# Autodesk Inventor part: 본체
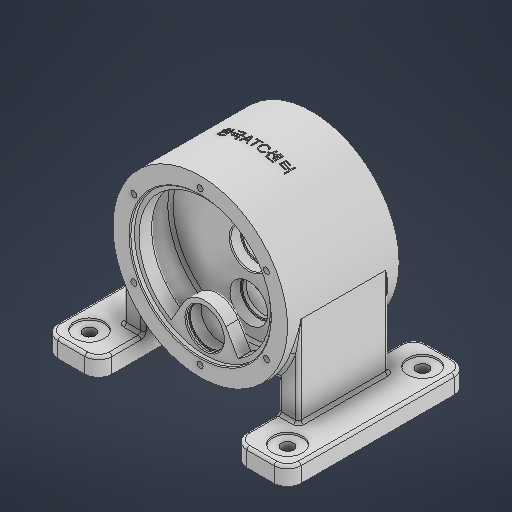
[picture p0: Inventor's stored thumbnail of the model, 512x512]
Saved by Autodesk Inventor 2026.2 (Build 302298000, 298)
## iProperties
Created: 2025-12
Part Number: 본체
Material: 일반
Document SubType Name: Modeling
Designer: PC2-07
Density: 1 g/cm^3
Appearance: 기본값
Author: PC2-07
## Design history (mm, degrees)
sketch "스케치1"
  geometry: C1 r 97 at (0, 0); 1 further point
  constraints: 1 centre point, 1 coincident
  dimensions: "d0" = 194 diameter of C1
extrude "돌출1" new body sketch "스케치1" stored distance "d1" = 124; taper "d2" = 0 deg
sketch "스케치2"
  geometry: L1 (97, -62)-(-97, -62) reference; L2 (-97, -62)-(-97, 62) reference; L3 (-97, 62)-(97, 62) reference; L4 (97, 62)-(97, -62) reference; L5 (0, 62)-(0, -62); L6 (78, 62)-(78, 57); L7 (78, 57)-(73, 57); L8 (73, 57)-(73, 43); L9 (76, 40)-(84, 40); L10 (87, 37)-(87, 11); L11 (84, 8)-(22, 8); L12 (21, 7)-(21, -3.4); L13 (20.4, -4)-(19, -4); L14 (19, -4)-(19, -8); L15 (19, -8)-(84, -8); L16 (87, -11)-(87, -37); L17 (84, -40)-(76, -40); L18 (73, -43)-(73, -57); L19 (73, -57)-(78, -57); L20 (78, -57)-(78, -62); L21 (22, 8)-(21, 7); A1 r 0.6 centre (20.4, -3.4) between (20.4, -4) and (21, -3.4); A2 r 3 centre (84, 37) between (87, 37) and (84, 40); A3 r 3 centre (84, 11) between (84, 8) and (87, 11); A4 r 3 centre (84, -11) between (87, -11) and (84, -8); A5 r 3 centre (84, -37) between (84, -40) and (87, -37); A6 r 3 centre (76, -43) between (76, -40) and (73, -43); A7 r 3 centre (76, 43) between (73, 43) and (76, 40); 6 further points
  constraints: 34 end point, 14 point on circle, 14 point on line, 14 tangent, 10 perpendicular, 7 centre point, 3 equal radius, 3 vertical, 2 midpoint, 1 horizontal
  dimensions: "d3" = 156 diameter of L6 L5; "d4" = 146 diameter of L8 L5; "d5" = 174 diameter of L10 L5; "d6" = 42 diameter of L12 L5; "d7" = 38 diameter of L14 L5; "d8" = 146 diameter of L18 L5; "d9" = 156 diameter of L20 L5; "d10" = 5 distance of L6.start L6.end; "d11" = 22 distance between parallel lines of L3 L9; "d12" = 32 distance of point (87, 40) point (87, 8); "d13" = 32 distance of point (87, -8) point (87, -40); "d14" = 5 distance of L19.end L20.end; "d16" = 22 distance between parallel lines of L1 L17; "d17" = 66 distance between parallel lines of L3 L13; "d18" = 0.6 radius of A1; "d19" = 3 radius of A2; "d20" = 3 radius of A6 (derived); "d21" = 3 radius of A7 (derived); "d22" = 1 distance of L11.end point (21, 8); "d23" = 1 distance of L12.start point (21, 8) (= d22)
revolve "회전1" sketch "스케치2" stored, may be unused: angle "d24" = 90 deg
sketch "스케치4"
  geometry: L1 (78, -62)-(78, -57) reference; L2 (78, -57)-(73, -57) reference; L3 (73, -57)-(73, -43) reference; L4 (76, -40)-(84, -40) reference; L5 (87, -37)-(87, -11) reference; L6 (84, -8)-(19, -8) reference; L7 (19, -8)-(19, -4) reference; L8 (19, -4)-(20.4, -4) reference; L9 (21, -3.4)-(21, 7) reference; L10 (21, 7)-(22, 8) reference; L11 (22, 8)-(84, 8) reference; L12 (87, 11)-(87, 37) reference; L13 (84, 40)-(76, 40) reference; L14 (73, 43)-(73, 57) reference; L15 (73, 57)-(78, 57) reference; L16 (78, 57)-(78, 62) reference; L17 (78, 62)-(97, 62) reference; L18 (97, 62)-(97, -62) reference; L19 (97, -62)-(78, -62) reference; L20 (-78, -57)-(-78, -62) reference; L21 (-78, -62)-(-97, -62) reference; L22 (-97, -62)-(-97, 62) reference; L23 (-97, 62)-(-78, 62) reference; L24 (-78, 62)-(-78, 57) reference; L25 (-78, 57)-(-73, 57) reference; L26 (-76, 40)-(-84, 40) reference; L27 (-87, 37)-(-87, 11) reference; L28 (-84, 8)-(-22, 8) reference; L29 (-22, 8)-(-21, 7) reference; L30 (-21, 7)-(-21, -3.4) reference; L31 (-20.4, -4)-(-19, -4) reference; L32 (-19, -4)-(-19, -8) reference; L33 (-19, -8)-(-84, -8) reference; L34 (-87, -11)-(-87, -37) reference; L35 (-84, -40)-(-76, -40) reference; L36 (-73, -43)-(-73, -57) reference; L37 (-73, -57)-(-78, -57) reference; L38 (0, 0)-(-52.5, 0); L39 (-52.5, 0)-(-52.5, 62); L40 (-52.5, 0)-(-52.5, -62); L41 (78, -62)-(-78, -62) reference; L42 (-31.5, 57)-(-31.5, 53.95); L43 (-31.5, 53.95)-(-30.25, 53.95); L44 (-30.25, 53.95)-(-30.25, 52); L45 (-30.25, 52)-(-31.5, 52); L46 (-31.5, 52)-(-31.5, 40); L47 (-73, 57)-(-73, 43) reference; A1 r 3 centre (76, -43) between (76, -40) and (73, -43) reference; A2 r 3 centre (84, -37) between (84, -40) and (87, -37) reference; A3 r 3 centre (84, -11) between (87, -11) and (84, -8) reference; A4 r 0.6 centre (20.4, -3.4) between (20.4, -4) and (21, -3.4) reference; A5 r 3 centre (84, 11) between (84, 8) and (87, 11) reference; A6 r 3 centre (84, 37) between (87, 37) and (84, 40) reference; A7 r 3 centre (76, 43) between (73, 43) and (76, 40) reference; A8 r 3 centre (-76, 43) between (-76, 40) and (-73, 43) reference; A9 r 3 centre (-84, 37) between (-84, 40) and (-87, 37) reference; A10 r 3 centre (-84, 11) between (-87, 11) and (-84, 8) reference; A11 r 0.6 centre (-20.4, -3.4) between (-21, -3.4) and (-20.4, -4) reference; A12 r 3 centre (-84, -11) between (-84, -8) and (-87, -11) reference; A13 r 3 centre (-84, -37) between (-87, -37) and (-84, -40) reference; A14 r 3 centre (-76, -43) between (-73, -43) and (-76, -40) reference
  constraints: 16 end point, 3 vertical, 2 horizontal, 2 perpendicular, 2 point on line
  dimensions: "d32" = 52.5 distance of L38.start L38.end; "d33" = 44.5 diameter of L44 L39; "d34" = 1.95 distance of L43.end L44.end; "d35" = 12 distance of L45.end L46.end; "d36" = 42 diameter of L46 L39; "d37" = 42 diameter of L42 L39
  node "절단 모서리 투영2"
node "작업 평면2"
sketch "스케치5"
  geometry: L1 (0, 0)-(0, -52.5); L2 (-23.383, -39)-(-49.148, -83.627); L3 (0, -52.5)-(0, -97); L4 (23.383, -39)-(49.148, -83.627); C1 r 84 at (0, 0) reference; C2 r 76 at (0, 0) reference; A1 r 27 centre (0, -52.5) between (23.383, -39) and (-23.383, -39); A2 r 97 centre (0, 0) between (-49.148, -83.627) and (0, -97) reference; 2 further points
  constraints: 8 end point, 4 point on circle, 2 symmetric about line, 2 vertical, 1 centre point, 1 coincident, 1 tangent
  dimensions: "d41" = 52.5 distance of L1.start L1.end; "d42" = 54 diameter of A1; "d43" = 30 deg angle of L2 L3
extrude "돌출3" join sketch "스케치5" distance "d44" = 17; taper "d45" = 0 deg
sketch "스케치6"
  geometry: L1 (0, 0)-(-52.5, 0); L2 (-52.5, 0)-(-52.5, 62); L3 (-78, 62)-(78, 62) reference; L4 (78, -62)-(78, -57) reference; L5 (78, -57)-(73, -57) reference; L6 (73, -57)-(73, -43) reference; L7 (76, -40)-(84, -40) reference; L8 (87, -37)-(87, -11) reference; L9 (84, -8)-(19, -8) reference; L10 (19, -8)-(19, -4) reference; L11 (19, -4)-(20.4, -4) reference; L12 (21, -3.4)-(21, 7) reference; L13 (21, 7)-(22, 8) reference; L14 (22, 8)-(84, 8) reference; L15 (87, 11)-(87, 37) reference; L16 (84, 40)-(76, 40) reference; L17 (73, 43)-(73, 57) reference; L18 (73, 57)-(78, 57) reference; L19 (78, 57)-(78, 62) reference; L20 (78, 62)-(97, 62) reference; L21 (97, 62)-(97, -62) reference; L22 (97, -62)-(78, -62) reference; L23 (-78, -57)-(-78, -62) reference; L24 (-78, -62)-(-97, -62) reference; L25 (-97, -62)-(-97, 62) reference; L26 (-97, 62)-(-78, 62) reference; L27 (-78, 62)-(-78, 57) reference; L28 (-78, 57)-(-25.5, 57) reference; L29 (-25.5, 57)-(-25.5, 40) reference; L30 (-25.5, 40)-(-84, 40) reference; L31 (-87, 37)-(-87, 11) reference; L32 (-84, 8)-(-22, 8) reference; L33 (-22, 8)-(-21, 7) reference; L34 (-21, 7)-(-21, -3.4) reference; L35 (-20.4, -4)-(-19, -4) reference; L36 (-19, -4)-(-19, -8) reference; L37 (-19, -8)-(-84, -8) reference; L38 (-87, -11)-(-87, -37) reference; L39 (-84, -40)-(-76, -40) reference; L40 (-73, -43)-(-73, -57) reference; L41 (-73, -57)-(-78, -57) reference; L42 (-31.5, 57)-(-31.5, 53.95); L43 (-31.5, 53.95)-(-30.25, 53.95); L44 (-30.25, 53.95)-(-30.25, 52); L45 (-30.25, 52)-(-31.5, 52); L46 (-31.5, 52)-(-31.5, 40); A1 r 3 centre (76, -43) between (76, -40) and (73, -43) reference; A2 r 3 centre (84, -37) between (84, -40) and (87, -37) reference; A3 r 3 centre (84, -11) between (87, -11) and (84, -8) reference; A4 r 0.6 centre (20.4, -3.4) between (20.4, -4) and (21, -3.4) reference; A5 r 3 centre (84, 11) between (84, 8) and (87, 11) reference; A6 r 3 centre (84, 37) between (87, 37) and (84, 40) reference; A7 r 3 centre (76, 43) between (73, 43) and (76, 40) reference; A8 r 3 centre (-84, 37) between (-84, 40) and (-87, 37) reference; A9 r 3 centre (-84, 11) between (-87, 11) and (-84, 8) reference; A10 r 0.6 centre (-20.4, -3.4) between (-21, -3.4) and (-20.4, -4) reference; A11 r 3 centre (-84, -11) between (-84, -8) and (-87, -11) reference; A12 r 3 centre (-84, -37) between (-87, -37) and (-84, -40) reference; A13 r 3 centre (-76, -43) between (-73, -43) and (-76, -40) reference; 2 further points
  constraints: 14 end point, 4 perpendicular, 3 point on line, 2 vertical, 1 horizontal
  dimensions: "d46" = 52.5 distance of L1.start L1.end; "d47" = 12 distance of L45.end L46.end; "d48" = 1.95 distance of L43.end L44.end; "d49" = 44.5 diameter of L44 L2; "d50" = 42 diameter of L46 L2; "d51" = 42 diameter of L42 L2
revolve "회전2" sketch "스케치6" stored, may be unused: angle "d52" = 90 deg
chamfer "모따기1" distance "d53" = 1; stored, may be unused: second distance "d54" = 2, angle "d55" = 45 deg
fillet "모깎기2" dims "d56" = 3
node "작업 평면3"
sketch "스케치7"
  geometry: L1 (-75, 100)-(-135, 100); L2 (-135, 100)-(-135, -100); L3 (-135, -100)-(-75, -100); L4 (-75, -100)-(-75, 100); L5 (75, 100)-(135, 100); L6 (135, 100)-(135, -100); L7 (135, -100)-(75, -100); L8 (75, -100)-(75, 100); 3 further points
  constraints: 16 end point, 4 parallel, 2 horizontal, 2 horizontal alignment, 2 midpoint, 2 perpendicular
  dimensions: "d58" = 60 distance of L5.start L5.end; "d59" = 60 distance of L1.start L1.end; "d60" = 75 distance from line of L4 point (0, 0); "d61" = 75 distance from line of L8 point (0, 0); "d62" = 200 distance of L1.end L2.end; "d63" = 200 distance of L5.end L6.end
extrude "돌출4" join sketch "스케치7" distance "d64" = 20; taper "d65" = 0 deg
fillet "모깎기3" dims "d66" = 15
sketch "스케치8"
  geometry: L1 (135, 85)-(135, -85) reference; L2 (120, -100)-(90, -100) reference; L3 (75, -85)-(75, 85) reference; L4 (90, 100)-(120, 100) reference; L5 (-75, 85)-(-75, -85) reference; L6 (-90, -100)-(-120, -100) reference; L7 (-135, -85)-(-135, 85) reference; L8 (-120, 100)-(-90, 100) reference; C1 r 16.5 at (110, -75); C2 r 16.5 at (-110, -75); C3 r 16.5 at (-110, 75); C4 r 16.5 at (110, 75); A1 r 15 centre (120, 85) between (135, 85) and (120, 100) reference; A2 r 15 centre (120, -85) between (120, -100) and (135, -85) reference; A3 r 15 centre (90, -85) between (75, -85) and (90, -100) reference; A4 r 15 centre (90, 85) between (90, 100) and (75, 85) reference; A5 r 15 centre (-90, 85) between (-75, 85) and (-90, 100) reference; A6 r 15 centre (-90, -85) between (-90, -100) and (-75, -85) reference; A7 r 15 centre (-120, -85) between (-135, -85) and (-120, -100) reference; A8 r 15 centre (-120, 85) between (-120, 100) and (-135, 85) reference; 1 further point
  constraints: 4 centre point
  dimensions: "d67" = 150 distance of C1.centre C4.centre; "d68" = 75 vertical distance of point (0, 0) C1.centre; "d69" = 110 horizontal distance of point (0, 0) C1.centre; "d70" = 220 distance of C2.centre C1.centre; "d71" = 33 diameter of C1; "d72" = 33 diameter of C4; "d73" = 33 diameter of C3; "d74" = 33 diameter of C2; "d75" = 150 distance of C3.centre C2.centre; "d76" = 75 vertical distance of point (0, 0) C3.centre; "d77" = 110 horizontal distance of point (0, 0) C3.centre; "d78" = 110 horizontal distance of point (0, 0) C4.centre
extrude "돌출5" cut sketch "스케치8" distance "d79" = 2; taper "d80" = 0 deg
sketch "스케치9"
  geometry: C1 r 16.5 at (0, 0) reference; C2 r 6.75 at (0, 0); C3 r 16.5 at (0, 150) reference; C4 r 6.75 at (0, 150); C5 r 16.5 at (-220, 150) reference; C6 r 6.75 at (-220, 150); C7 r 16.5 at (-220, 0) reference; C8 r 6.75 at (-220, 0); 1 further point
  constraints: 4 centre point, 4 coincident
  dimensions: "d81" = 13.5 diameter of C8; "d82" = 13.5 diameter of C2; "d83" = 13.5 diameter of C4; "d84" = 13.5 diameter of C6
extrude "돌출6" cut sketch "스케치9" extent not by distance; stored distance "d85" = 0; taper "d86" = 0 deg
sketch "스케치10"
  geometry: L1 (75, 85)-(75, -85) reference; L2 (75, 50)-(97, 50); L3 (97, 50)-(97, -50); L4 (97, -50)-(75, -50); L5 (135, 85)-(135, -85) reference; L6 (120, -100)-(90, -100) reference; L7 (75, -85)-(75, 85) reference; L8 (90, 100)-(120, 100) reference; L9 (-75, 85)-(-75, -85) reference; L10 (-90, -100)-(-120, -100) reference; L11 (-135, -85)-(-135, 85) reference; L12 (-120, 100)-(-90, 100) reference; L13 (-75, 50)-(-97, 50); L14 (-97, 50)-(-97, -50); L15 (-97, -50)-(-75, -50); C1 r 16.5 at (110, 75) reference; C2 r 16.5 at (110, -75) reference; C3 r 16.5 at (-110, -75) reference; C4 r 16.5 at (-110, 75) reference; A1 r 15 centre (120, 85) between (135, 85) and (120, 100) reference; A2 r 15 centre (120, -85) between (120, -100) and (135, -85) reference; A3 r 15 centre (90, -85) between (75, -85) and (90, -100) reference; A4 r 15 centre (90, 85) between (90, 100) and (75, 85) reference; A5 r 15 centre (-90, 85) between (-75, 85) and (-90, 100) reference; A6 r 15 centre (-90, -85) between (-90, -100) and (-75, -85) reference; A7 r 15 centre (-120, -85) between (-135, -85) and (-120, -100) reference; A8 r 15 centre (-120, 85) between (-120, 100) and (-135, 85) reference; 3 further points
  constraints: 12 end point, 4 perpendicular, 4 point on line, 2 horizontal, 2 horizontal alignment, 2 midpoint
  dimensions: "d87" = 100 distance of L13.end L14.end; "d88" = 22 distance of L2.start L2.end; "d89" = 22 distance of L13.start L13.end; "d90" = 100 distance of L2.end L3.end
extrude "돌출7" join sketch "스케치10" stored distance "d91" = 100; taper "d92" = 0 deg
sketch "스케치11" dims "d93" = 170
  geometry: C1 r 97 at (0, 0) reference; 3 further points
  constraints: 2 vertical alignment, 1 coincident, 2 other
hole "구멍1" sketch "스케치11" at (0, 85) diameter "d94" = 6.647; stored, may be unused: countersink angle "d98" = 90 deg, drill point angle "d100" = 118 deg; dims "d95" = 16, "d96" = 4, "d97" = 2, "d99" = 18
sketch "스케치12"
  geometry: L1 (78, 61)-(79, 62) reference; L2 (79, 62)-(81.677, 62) reference; L3 (81.677, 62)-(81.677, 44) reference; L4 (81.677, 44)-(85, 42.003) reference; L5 (85, 42.003)-(88.323, 44) reference; L6 (88.323, 44)-(88.323, 62) reference; L7 (88.323, 62)-(97, 62) reference; L8 (97, 62)-(97, -62) reference; L9 (97, -62)-(88.323, -62) reference; L10 (88.323, -62)-(88.323, -44) reference; L11 (88.323, -44)-(85, -42.003) reference; L12 (85, -42.003)-(81.677, -44) reference; L13 (81.677, -44)-(81.677, -62) reference; L14 (81.677, -62)-(79, -62) reference; L15 (79, -62)-(78, -61) reference; L16 (78, -61)-(78, -57) reference; L17 (78, -57)-(73, -57) reference; L18 (73, -57)-(73, -43) reference; L19 (76, -40)-(84, -40) reference; L20 (87, -37)-(87, -11) reference; L21 (84, -8)-(19, -8) reference; L22 (19, -8)-(19, -4) reference; L23 (19, -4)-(20.4, -4) reference; L24 (21, -3.4)-(21, 7) reference; L25 (21, 7)-(22, 8) reference; L26 (22, 8)-(84, 8) reference; L27 (87, 11)-(87, 37) reference; L28 (84, 40)-(76, 40) reference; L29 (73, 43)-(73, 57) reference; L30 (73, 57)-(78, 57) reference; L31 (78, 57)-(78, 61) reference; L32 (-74.75, 52)-(-73.5, 52) reference; L33 (-73.5, 52)-(-73.5, 40) reference; L34 (-73.5, 40)-(-84, 40) reference; L35 (-87, 37)-(-87, 11) reference; L36 (-84, 8)-(-22, 8) reference; L37 (-22, 8)-(-21, 7) reference; L38 (-21, 7)-(-21, -3.4) reference; L39 (-20.4, -4)-(-19, -4) reference; L40 (-19, -4)-(-19, -8) reference; L41 (-19, -8)-(-84, -8) reference; L42 (-87, -11)-(-87, -37) reference; L43 (-84, -40)-(-76, -40) reference; L44 (-73, -43)-(-73, -57) reference; L45 (-73, -57)-(-78, -57) reference; L46 (-78, -57)-(-78, -61) reference; L47 (-78, -61)-(-79, -62) reference; L48 (-79, -62)-(-81.677, -62) reference; L49 (-81.677, -62)-(-81.677, -44) reference; L50 (-81.677, -44)-(-85, -42.003) reference; L51 (-85, -42.003)-(-88.323, -44) reference; L52 (-88.323, -44)-(-88.323, -62) reference; L53 (-88.323, -62)-(-97, -62) reference; L54 (-97, -62)-(-97, 62) reference; L55 (-97, 62)-(-88.323, 62) reference; L56 (-88.323, 62)-(-88.323, 44) reference; L57 (-88.323, 44)-(-85, 42.003) reference; L58 (-85, 42.003)-(-81.677, 44) reference; L59 (-81.677, 44)-(-81.677, 62) reference; L60 (-81.677, 62)-(-79, 62) reference; L61 (-79, 62)-(-78, 61) reference; L62 (-78, 61)-(-78, 57) reference; L63 (-78, 57)-(-74.5, 57) reference; L64 (-74.5, 57)-(-73.5, 56) reference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; A1 r 3 centre (76, -43) between (76, -40) and (73, -43) reference; A2 r 3 centre (84, -37) between (84, -40) and (87, -37) reference; A3 r 3 centre (84, -11) between (87, -11) and (84, -8) reference; A4 r 0.6 centre (20.4, -3.4) between (20.4, -4) and (21, -3.4) reference; A5 r 3 centre (84, 11) between (84, 8) and (87, 11) reference; A6 r 3 centre (84, 37) between (87, 37) and (84, 40) reference; A7 r 3 centre (76, 43) between (73, 43) and (76, 40) reference; A8 r 3 centre (-84, 37) between (-84, 40) and (-87, 37) reference; A9 r 3 centre (-84, 11) between (-87, 11) and (-84, 8) reference; A10 r 0.6 centre (-20.4, -3.4) between (-21, -3.4) and (-20.4, -4) reference; A11 r 3 centre (-84, -11) between (-84, -8) and (-87, -11) reference; A12 r 3 centre (-84, -37) between (-87, -37) and (-84, -40) reference; A13 r 3 centre (-76, -43) between (-73, -43) and (-76, -40) reference; A14 r 3 centre (-28.5, 43) between (-28.5, 40) and (-25.5, 43) reference; A15 r 0.6 centre (-32.1, -3.4) between (-32.1, -4) and (-31.5, -3.4)
  constraints: 12 end point, 4 point on line, 3 perpendicular, 2 point on circle, 2 tangent, 2 vertical, 1 centre point, 1 parallel
  dimensions: "d104" = 52.5 distance of L77.start L77.end; "d105" = 42 diameter of L80 L78; "d106" = 66 distance between parallel lines of L83 L81; "d107" = 38 diameter of L82 L78; "d108" = 0.6 radius of A15
revolve "회전3" sketch "스케치12" stored, may be unused: angle "d109" = 90 deg
sketch "스케치13"
  geometry: L1 (75, -120)-(75, -61.514) reference; L2 (-75, -61.514)-(-75, -120) reference; L3 (-75, -120)-(-135, -120) reference; L4 (-135, -120)-(-135, -100) reference; L5 (-135, -100)-(-97, -100) reference; L6 (-97, -100)-(-97, 0) reference; L7 (97, 0)-(97, -100) reference; L8 (97, -100)-(135, -100) reference; L9 (135, -100)-(135, -120) reference; L10 (135, -120)-(75, -120) reference; L11 (-75, -112)-(-36.6, -89.83); C1 r 21 at (0, -52.5) reference; C2 r 21 at (0, 0) reference; A1 r 97 centre (0, 0) between (-75, -61.514) and (75, -61.514) reference; A2 r 97 centre (0, 0) between (97, 0) and (-97, 0) reference; 1 further point
  constraints: 2 end point, 1 point on circle, 1 point on line
  dimensions: "d110" = 60 deg angle of L11 L2; "d111" = 8 distance from line of L3 L11.start
extrude "돌출8" join sketch "스케치13" stored distance "d112" = 12; taper "d113" = 0 deg
fillet "모깎기4" dims "d114" = 3
fillet "모깎기5" dims "d115" = 3
fillet "모깎기6" dims "d116" = 3
fillet "모깎기7" dims "d117" = 3
fillet "모깎기8" dims "d118" = 3
fillet "모깎기9" dims "d119" = 3
sketch "스케치14"
  geometry: 2 further points
  constraints: 2 coincident, 1 other
feature "엠보싱1" sketch "스케치14" dims "d1" = 124, "d14" = 5, "d120" = 0.5, "d121" = 0
node "솔리드1"
pattern_circular "원형 패턴1" dims angle "d102" = 360 deg
mirror "미러1"
mirror "미러2"
node "절단 모서리 투영1"
node "절단 모서리 투영3"
node "절단 모서리 투영4"
node "절단 모서리 투영5"
node "절단 모서리 투영6"
node "절단 모서리 투영7"
node "절단 모서리 투영8"
other parameters: "d26" = 54, "d40" = -22
